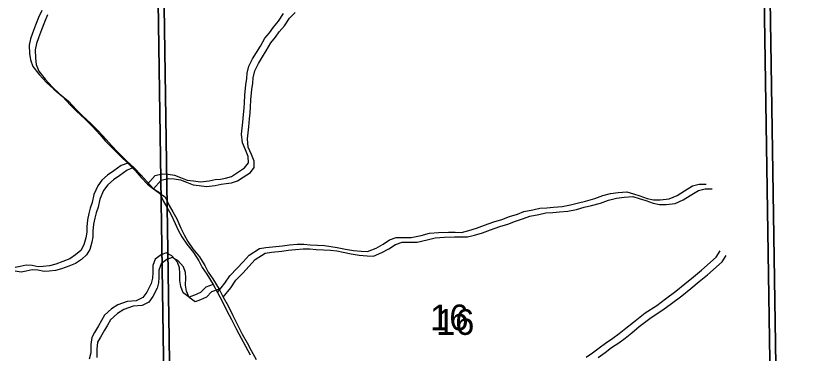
# Model space of a CAD drawing. Extents: x -21.1 to 50.3, y 0 to 22.1.
# Drawn here: x 45.942 to 47.215, y 17.109 to 17.658 of the extents above; entities that cross this region are included whole.
import ezdxf

# ---------------------------------------------------------------- set-up
doc = ezdxf.new("R2010")
doc.units = 0
for name, color, linetype in [('GM_X_Major_River', 7, 'Continuous'), ('GM_X_Minor_River', 7, 'Continuous'), ('GM_X_Section', 7, 'Continuous'), ('GM_X_Section_Text', 7, 'Continuous')]:
    doc.layers.add(name, color=color, linetype=linetype)

msp = doc.modelspace()

# ---------------------------------------------------------------- linework, layer by layer
at = {"layer": 'GM_X_Major_River'}
for points in [[(45.9842, 17.6666), (45.9793, 17.6548), (45.9741, 17.6423), (45.9693, 17.6297), (45.9659, 17.6202), (45.9641, 17.6099), (45.9642, 17.5963), (45.9658, 17.586), (45.9697, 17.5754), (45.9801, 17.5622), (45.9923, 17.5494), (46.0038, 17.5385), (46.0183, 17.5265), (46.0309, 17.5126), (46.0409, 17.5028), (46.0543, 17.49), (46.0661, 17.4783), (46.0791, 17.464), (46.0879, 17.4542), (46.0979, 17.444), (46.1124, 17.4297), (46.1243, 17.4184), (46.1361, 17.406), (46.1461, 17.3951), (46.156, 17.3842), (46.166, 17.3767), (46.1755, 17.3707), (46.1817, 17.3567), (46.1874, 17.3468), (46.194, 17.3351), (46.2009, 17.32), (46.206, 17.3094), (46.2121, 17.2985), (46.2202, 17.2864), (46.2309, 17.2732), (46.2398, 17.2592), (46.2451, 17.2486), (46.2524, 17.2377), (46.2628, 17.2207), (46.2698, 17.2079), (46.2775, 17.1939), (46.2852, 17.178), (46.2925, 17.164), (46.3006, 17.1478), (46.3083, 17.1334), (46.3152, 17.1209), (46.3229, 17.1066)], [(45.9938, 17.6591), (45.989, 17.6473), (45.9838, 17.6348), (45.9789, 17.6222), (45.9756, 17.6127), (45.9738, 17.6024), (45.9739, 17.5888), (45.9755, 17.5785), (45.9794, 17.5679), (45.9897, 17.5547), (46.0019, 17.5419), (46.0134, 17.531), (46.0279, 17.519), (46.0406, 17.5051), (46.0505, 17.4953), (46.0639, 17.4825), (46.0758, 17.4708), (46.0888, 17.4565), (46.0976, 17.4467), (46.1075, 17.4365), (46.1221, 17.4222), (46.1339, 17.4109), (46.1458, 17.3985), (46.1557, 17.3876), (46.1657, 17.3767), (46.1756, 17.3692), (46.1851, 17.3632), (46.1913, 17.3492), (46.1971, 17.3393), (46.2036, 17.3276), (46.2106, 17.3125), (46.2156, 17.3019), (46.2218, 17.291), (46.2298, 17.2789), (46.2405, 17.2657), (46.2494, 17.2517), (46.2548, 17.2411), (46.2621, 17.2302), (46.2725, 17.2132), (46.2794, 17.2004), (46.2871, 17.1864), (46.2948, 17.1705), (46.3021, 17.1565), (46.3102, 17.1403), (46.3179, 17.1259), (46.3249, 17.1134), (46.3326, 17.0991)]]:
    msp.add_lwpolyline(points, dxfattribs=at)
at = {"layer": 'GM_X_Minor_River'}
for points in [[(46.156, 17.3842), (46.1687, 17.3979), (46.1801, 17.4006), (46.1896, 17.4003), (46.1999, 17.3985), (46.2098, 17.3947), (46.2209, 17.3906), (46.2308, 17.3895), (46.2422, 17.3877), (46.2563, 17.3893), (46.2662, 17.3916), (46.2746, 17.3924), (46.2829, 17.3936), (46.2928, 17.3967), (46.3023, 17.4028), (46.314, 17.4105), (46.3201, 17.4189), (46.32, 17.4288), (46.3154, 17.4397), (46.3104, 17.4515), (46.3092, 17.4655), (46.3099, 17.475), (46.3113, 17.4846), (46.3124, 17.4975), (46.3135, 17.5074), (46.3138, 17.5165), (46.3145, 17.5286), (46.3159, 17.5454), (46.3174, 17.5556), (46.3181, 17.5644), (46.3211, 17.5758), (46.3267, 17.5876), (46.3335, 17.5983), (46.3396, 17.6082), (46.3471, 17.6215), (46.3547, 17.6303), (46.3607, 17.6394), (46.369, 17.649), (46.3773, 17.6616)], [(46.1657, 17.3767), (46.1783, 17.3904), (46.1897, 17.3931), (46.1993, 17.3928), (46.2096, 17.391), (46.2195, 17.3872), (46.2305, 17.3831), (46.2404, 17.382), (46.2519, 17.3802), (46.2659, 17.3818), (46.2758, 17.3841), (46.2842, 17.3849), (46.2926, 17.3861), (46.3024, 17.3892), (46.3119, 17.3953), (46.3237, 17.403), (46.3297, 17.4114), (46.3297, 17.4213), (46.325, 17.4322), (46.32, 17.444), (46.3188, 17.458), (46.3195, 17.4675), (46.321, 17.4771), (46.322, 17.49), (46.3231, 17.4999), (46.3235, 17.509), (46.3242, 17.5211), (46.3256, 17.5379), (46.3271, 17.5481), (46.3278, 17.5569), (46.3307, 17.5683), (46.3364, 17.5801), (46.3432, 17.5908), (46.3492, 17.6007), (46.3568, 17.614), (46.3643, 17.6228), (46.3704, 17.6319), (46.3787, 17.6415), (46.387, 17.6541), (46.3961, 17.6632)], [(46.1243, 17.4184), (46.1134, 17.4143), (46.1017, 17.4055), (46.0911, 17.3986), (46.082, 17.3906), (46.0752, 17.3814), (46.0692, 17.367), (46.0662, 17.3544), (46.0632, 17.3449), (46.061, 17.3365), (46.0587, 17.3263), (46.0576, 17.3149), (46.0577, 17.3061), (46.0562, 17.297), (46.0529, 17.2852), (46.0476, 17.2764), (46.0393, 17.2692), (46.0298, 17.2627), (46.0188, 17.2584), (46.007, 17.2538), (45.9971, 17.2511), (45.9868, 17.2503), (45.9785, 17.2498), (45.9686, 17.2517), (45.959, 17.2524), (45.9495, 17.2501), (45.9412, 17.2485)], [(46.1339, 17.4109), (46.1231, 17.4068), (46.1113, 17.398), (46.1007, 17.3911), (46.0916, 17.3831), (46.0848, 17.3739), (46.0788, 17.3595), (46.0758, 17.3469), (46.0728, 17.3374), (46.0706, 17.329), (46.0684, 17.3188), (46.0673, 17.3074), (46.0673, 17.2986), (46.0659, 17.2895), (46.0625, 17.2777), (46.0572, 17.2689), (46.0489, 17.2617), (46.0394, 17.2552), (46.0284, 17.2509), (46.0166, 17.2463), (46.0067, 17.2436), (45.9965, 17.2428), (45.9881, 17.2423), (45.9782, 17.2442), (45.9687, 17.2449), (45.9592, 17.2426), (45.9508, 17.241), (45.9413, 17.2428)], [(46.2698, 17.2079), (46.282, 17.223), (46.2899, 17.2352), (46.302, 17.2475), (46.3115, 17.2578), (46.3213, 17.2688), (46.338, 17.2792), (46.3483, 17.2811), (46.3646, 17.2828), (46.3753, 17.284), (46.3871, 17.2855), (46.3996, 17.2864), (46.4103, 17.2864), (46.4206, 17.2853), (46.4324, 17.285), (46.4438, 17.2843), (46.4541, 17.2829), (46.4644, 17.281), (46.4777, 17.2784), (46.4907, 17.2762), (46.5036, 17.2752), (46.5139, 17.2745), (46.5276, 17.2802), (46.5389, 17.2864), (46.5496, 17.2933), (46.5602, 17.2975), (46.5724, 17.2972), (46.5846, 17.2973), (46.6009, 17.3008), (46.6142, 17.3043), (46.629, 17.3055), (46.6454, 17.306), (46.6564, 17.306), (46.6667, 17.3057), (46.6781, 17.3088), (46.691, 17.3123), (46.704, 17.3173), (46.7192, 17.3227), (46.7321, 17.3266), (46.7446, 17.3316), (46.7575, 17.3355), (46.7678, 17.3397), (46.7822, 17.3421), (46.794, 17.3448), (46.8051, 17.3456), (46.8161, 17.3464), (46.8298, 17.3476), (46.8435, 17.3504), (46.8564, 17.3539), (46.8682, 17.3566), (46.883, 17.3605), (46.8959, 17.3655), (46.9085, 17.369), (46.921, 17.3706), (46.9351, 17.3714), (46.9458, 17.3684), (46.9564, 17.365), (46.9683, 17.3606), (46.9785, 17.3587), (46.9892, 17.3584), (47.004, 17.36), (47.017, 17.3658), (47.0287, 17.373), (47.042, 17.3811), (47.0526, 17.3842), (47.0641, 17.3839)], [(46.2794, 17.2004), (46.2916, 17.2155), (46.2995, 17.2277), (46.3117, 17.24), (46.3211, 17.2503), (46.3309, 17.2613), (46.3476, 17.2717), (46.3579, 17.2736), (46.3743, 17.2753), (46.3849, 17.2765), (46.3967, 17.278), (46.4093, 17.2789), (46.4199, 17.2789), (46.4302, 17.2778), (46.442, 17.2775), (46.4534, 17.2768), (46.4637, 17.2754), (46.474, 17.2735), (46.4873, 17.2709), (46.5003, 17.2687), (46.5132, 17.2677), (46.5235, 17.267), (46.5372, 17.2727), (46.5486, 17.2789), (46.5592, 17.2858), (46.5698, 17.29), (46.582, 17.2897), (46.5942, 17.2898), (46.6105, 17.2933), (46.6238, 17.2968), (46.6387, 17.298), (46.655, 17.2985), (46.6661, 17.2985), (46.6764, 17.2982), (46.6878, 17.3013), (46.7007, 17.3048), (46.7136, 17.3098), (46.7288, 17.3152), (46.7417, 17.3191), (46.7542, 17.3241), (46.7672, 17.328), (46.7774, 17.3322), (46.7919, 17.3346), (46.8037, 17.3373), (46.8147, 17.3381), (46.8257, 17.3389), (46.8394, 17.3401), (46.8531, 17.3429), (46.866, 17.3464), (46.8778, 17.3491), (46.8926, 17.353), (46.9056, 17.358), (46.9181, 17.3615), (46.9306, 17.3631), (46.9447, 17.3639), (46.9554, 17.3609), (46.9661, 17.3575), (46.9779, 17.3531), (46.9882, 17.3512), (46.9988, 17.3509), (47.0137, 17.3525), (47.0266, 17.3583), (47.0383, 17.3655), (47.0516, 17.3736), (47.0623, 17.3767), (47.0737, 17.3764)], [(46.2628, 17.2207), (46.2508, 17.2164), (46.2425, 17.208), (46.2326, 17.2034), (46.2239, 17.2003), (46.2143, 17.2071), (46.2101, 17.2177), (46.2085, 17.2276), (46.2088, 17.2393), (46.2084, 17.2481), (46.2049, 17.2572), (46.1957, 17.2674), (46.1865, 17.2723), (46.1782, 17.2692), (46.1687, 17.2619), (46.165, 17.2516), (46.165, 17.2399), (46.1643, 17.2311), (46.1621, 17.2227), (46.1549, 17.2087), (46.1485, 17.1999), (46.1379, 17.1945), (46.1234, 17.1933), (46.1078, 17.1879), (46.0976, 17.1814), (46.0862, 17.171), (46.0813, 17.1623), (46.0764, 17.1539), (46.07, 17.1428), (46.0655, 17.1345), (46.064, 17.1234), (46.0641, 17.1098), (46.0615, 17.0995)], [(46.8688, 17.1028), (46.8791, 17.1097), (46.8904, 17.1181), (46.9007, 17.1258), (46.9124, 17.1335), (46.9227, 17.1411), (46.9337, 17.1499), (46.9458, 17.1599), (46.9651, 17.1748), (46.9841, 17.187), (46.9981, 17.1974), (47.0148, 17.21), (47.0296, 17.2219), (47.0432, 17.2333), (47.0565, 17.2444), (47.0803, 17.2651), (47.0867, 17.2757)], [(46.2725, 17.2132), (46.2604, 17.2089), (46.2521, 17.2005), (46.2422, 17.1959), (46.2335, 17.1928), (46.2239, 17.1996), (46.2197, 17.2102), (46.2181, 17.2201), (46.2184, 17.2318), (46.218, 17.2406), (46.2145, 17.2497), (46.2053, 17.2599), (46.1962, 17.2648), (46.1878, 17.2617), (46.1783, 17.2544), (46.1746, 17.2441), (46.1747, 17.2324), (46.174, 17.2236), (46.1717, 17.2152), (46.1646, 17.2012), (46.1581, 17.1924), (46.1475, 17.187), (46.1331, 17.1858), (46.1175, 17.1804), (46.1072, 17.1739), (46.0959, 17.1635), (46.091, 17.1548), (46.0861, 17.1464), (46.0797, 17.1353), (46.0751, 17.127), (46.0737, 17.1159), (46.0738, 17.1023)], [(46.8887, 17.1022), (46.9001, 17.1106), (46.9103, 17.1183), (46.9221, 17.126), (46.9323, 17.1336), (46.9433, 17.1424), (46.9554, 17.1524), (46.9748, 17.1673), (46.9937, 17.1795), (47.0077, 17.1899), (47.0244, 17.2025), (47.0392, 17.2144), (47.0528, 17.2258), (47.0661, 17.2369), (47.09, 17.2576), (47.0964, 17.2682)]]:
    msp.add_lwpolyline(points, dxfattribs=at)
at = {"layer": 'GM_X_Section'}
for points in [[(46.1737, 17.6801), (46.1885, 16.6701), (45.1628, 16.6817), (45.1486, 17.7019), (45.7604, 17.6964)], [(47.1584, 17.6908), (48.171, 17.7091), (48.1855, 16.6839), (47.1739, 16.679)], [(46.1834, 17.6726), (46.1982, 16.6626), (45.1724, 16.6742), (45.1583, 17.6944), (45.7701, 17.6889)], [(46.1737, 17.6801), (47.1584, 17.6908), (47.1739, 16.679), (46.1885, 16.6701)], [(47.168, 17.6833), (48.1806, 17.7016), (48.1952, 16.6764), (47.1836, 16.6715)], [(46.1834, 17.6726), (47.168, 17.6833), (47.1836, 16.6715), (46.1982, 16.6626)]]:
    msp.add_lwpolyline(points, close=True, dxfattribs=at)

# ---------------------------------------------------------------- texts
at = {"layer": 'GM_X_Section_Text'}
for p in [(46.6155, 17.1465), (46.6251, 17.139)]:
    msp.add_text('16', height=0.04186, rotation=0, dxfattribs=at).set_placement(p)

doc.saveas('drawing.dxf')
